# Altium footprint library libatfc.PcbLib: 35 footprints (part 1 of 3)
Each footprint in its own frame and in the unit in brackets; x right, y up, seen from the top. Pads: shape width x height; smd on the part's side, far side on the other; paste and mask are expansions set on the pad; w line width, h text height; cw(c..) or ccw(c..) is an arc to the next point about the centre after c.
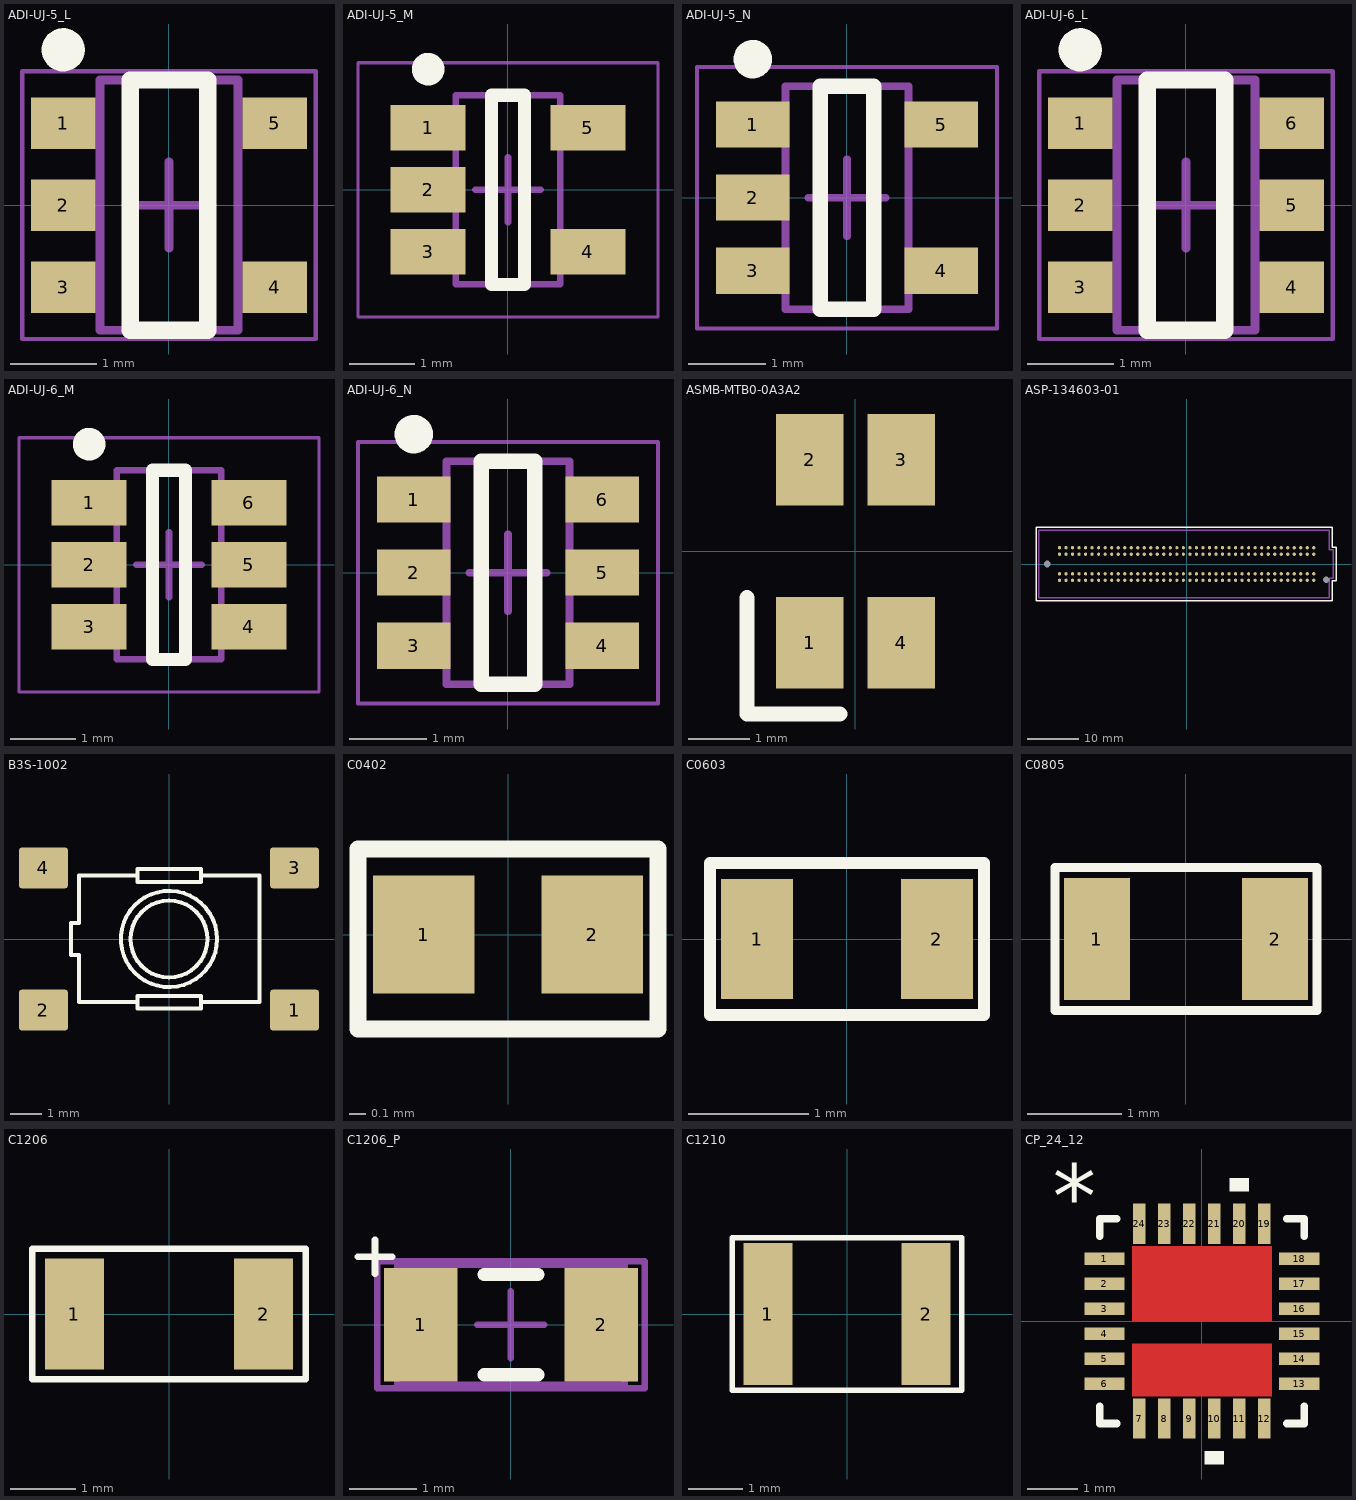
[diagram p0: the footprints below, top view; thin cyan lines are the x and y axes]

## ADI-UJ-5_L [mm] "SOT23, 5-Leads, Body 2.9x1.6mm, Pitch 0.95mm, IPC High Density"
height 1
pads (5):
  rect 0.75x0.6 smd: 1(-1.225,0.95) 2(-1.225,0) 3(-1.225,-0.95) 4(1.225,-0.95) 5(1.225,0.95)
Top Overlay:
  circle w0.25: c-1.225,1.8 r0.125
  lines w0.2: -0.45,-1.45 0.45,-1.45 0.45,1.45 -0.45,1.45 -0.45,-1.45
Mechanical 13:
  lines w0.1: -0.8,-1.45 -0.8,1.45 0.8,1.45 0.8,-1.45 -0.8,-1.45
Mechanical 15:
  lines w0.05: -1.7,-1.55 -1.7,1.55 1.7,1.55 1.7,-1.55 -1.7,-1.55
  lines w0.1: -0.5,0 0.5,0 ; 0,-0.5 0,0.5
3D body: height 1, standoff 0, extent -0.8,-1.45 0.8,1.45

## ADI-UJ-5_M [mm] "SOT23, 5-Leads, Body 2.9x1.6mm, Pitch 0.95mm, IPC Low Density"
height 1
pads (5):
  rect 1.15x0.7 smd: 1(-1.225,0.95) 2(-1.225,0) 3(-1.225,-0.95) 4(1.225,-0.95) 5(1.225,0.95)
Top Overlay:
  circle w0.25: c-1.225,1.85 r0.125
  lines w0.2: -0.25,-1.45 0.25,-1.45 0.25,1.45 -0.25,1.45 -0.25,-1.45
Mechanical 13:
  lines w0.1: -0.8,-1.45 -0.8,1.45 0.8,1.45 0.8,-1.45 -0.8,-1.45
Mechanical 15:
  lines w0.05: -2.3,-1.95 -2.3,1.95 2.3,1.95 2.3,-1.95 -2.3,-1.95
  lines w0.1: -0.5,0 0.5,0 ; 0,-0.5 0,0.5
3D body: height 1, standoff 0, extent -0.8,-1.45 0.8,1.45

## ADI-UJ-5_N [mm] "SOT23, 5-Leads, Body 2.9x1.6mm, Pitch 0.95mm, IPC Medium Density"
height 1
pads (5):
  rect 0.95x0.6 smd: 1(-1.225,0.95) 2(-1.225,0) 3(-1.225,-0.95) 4(1.225,-0.95) 5(1.225,0.95)
Top Overlay:
  circle w0.25: c-1.225,1.8 r0.125
  lines w0.2: -0.35,-1.45 -0.35,1.45 0.35,1.45 0.35,-1.45 -0.35,-1.45
Mechanical 13:
  lines w0.1: -0.8,-1.45 0.8,-1.45 0.8,1.45 -0.8,1.45 -0.8,-1.45
Mechanical 15:
  lines w0.05: -1.95,-1.7 1.95,-1.7 1.95,1.7 -1.95,1.7 -1.95,-1.7
  lines w0.1: -0.5,0 0.5,0 ; 0,-0.5 0,0.5
3D body: height 1, standoff 0, extent -0.8,-1.45 0.8,1.45

## ADI-UJ-6_L [mm] "SOT23, 6-Leads, Body 2.9x1.6mm, Pitch 0.95mm, IPC High Density"
height 1
pads (6):
  rect 0.75x0.6 smd: 1(-1.225,0.95) 2(-1.225,0) 3(-1.225,-0.95) 4(1.225,-0.95) 5(1.225,0) 6(1.225,0.95)
Top Overlay:
  circle w0.25: c-1.225,1.8 r0.125
  lines w0.2: -0.45,-1.45 0.45,-1.45 0.45,1.45 -0.45,1.45 -0.45,-1.45
Mechanical 13:
  lines w0.1: -0.8,-1.45 -0.8,1.45 0.8,1.45 0.8,-1.45 -0.8,-1.45
Mechanical 15:
  lines w0.05: -1.7,-1.55 -1.7,1.55 1.7,1.55 1.7,-1.55 -1.7,-1.55
  lines w0.1: -0.5,0 0.5,0 ; 0,-0.5 0,0.5
3D body: height 1, standoff 0.1, extent -0.8,-1.45 0.8,1.45

## ADI-UJ-6_M [mm] "SOT23, 6-Leads, Body 2.9x1.6mm, Pitch 0.95mm, IPC Low Density"
height 1
pads (6):
  rect 1.15x0.7 smd: 1(-1.225,0.95) 2(-1.225,0) 3(-1.225,-0.95) 4(1.225,-0.95) 5(1.225,0) 6(1.225,0.95)
Top Overlay:
  circle w0.25: c-1.225,1.85 r0.125
  lines w0.2: -0.25,-1.45 0.25,-1.45 0.25,1.45 -0.25,1.45 -0.25,-1.45
Mechanical 13:
  lines w0.1: -0.8,-1.45 -0.8,1.45 0.8,1.45 0.8,-1.45 -0.8,-1.45
Mechanical 15:
  lines w0.05: -2.3,-1.95 -2.3,1.95 2.3,1.95 2.3,-1.95 -2.3,-1.95
  lines w0.1: -0.5,0 0.5,0 ; 0,-0.5 0,0.5
3D body: height 1, standoff 0.1, extent -0.8,-1.45 0.8,1.45

## ADI-UJ-6_N [mm] "SOT23, 6-Leads, Body 2.9x1.6mm, Pitch 0.95mm, IPC Medium Density"
height 1
pads (6):
  rect 0.95x0.6 smd: 1(-1.225,0.95) 2(-1.225,0) 3(-1.225,-0.95) 4(1.225,-0.95) 5(1.225,0) 6(1.225,0.95)
Top Overlay:
  circle w0.25: c-1.225,1.8 r0.125
  lines w0.2: -0.35,-1.45 0.35,-1.45 0.35,1.45 -0.35,1.45 -0.35,-1.45
Mechanical 13:
  lines w0.1: -0.8,-1.45 -0.8,1.45 0.8,1.45 0.8,-1.45 -0.8,-1.45
Mechanical 15:
  lines w0.05: -1.95,-1.7 -1.95,1.7 1.95,1.7 1.95,-1.7 -1.95,-1.7
  lines w0.1: -0.5,0 0.5,0 ; 0,-0.5 0,0.5
3D body: height 1, standoff 0.1, extent -0.8,-1.45 0.8,1.45

## ASMB-MTB0-0A3A2 [mm]
pads (4):
  rect 1.1x1.5 smd: 1(-0.75,-1.5) 2(-0.75,1.5) 3(0.75,1.5) 4(0.75,-1.5)
Top Overlay:
  lines w0.254: -1.778,-0.762 -1.778,-2.667 -0.254,-2.667
3D body "User Library-ASMB-MTB0-0A3A2.STEP": height 1.9, standoff 0, extent -1.395,-1.685 1.405,1.815

## ASP-134603-01 [mil]
pads (162):
  round 25 smd paste+5 mask+2: C1(975,-125) C2(925,-125) C3(875,-125) C4(825,-125) C5(775,-125) C6(725,-125) C7(675,-125) C8(625,-125) C9(575,-125) C10(525,-125) C11(475,-125) C12(425,-125) C13(375,-125) C14(325,-125) C15(275,-125) C16(225,-125) C17(175,-125) C18(125,-125) C19(75,-125) C20(25,-125) C21(-25,-125) C22(-75,-125) C23(-125,-125) C24(-175,-125) C25(-225,-125) C26(-275,-125) C27(-325,-125) C28(-375,-125) C29(-425,-125) C30(-475,-125) C31(-525,-125) C32(-575,-125) C33(-625,-125) C34(-675,-125) C35(-725,-125) C36(-775,-125) C37(-825,-125) C38(-875,-125) C39(-925,-125) C40(-975,-125) D1(975,-75) D2(925,-75) D3(875,-75) D4(825,-75) D5(775,-75) D6(725,-75) D7(675,-75) D8(625,-75) D9(575,-75) D10(525,-75) D11(475,-75) D12(425,-75) D13(375,-75) D14(325,-75) D15(275,-75) D16(225,-75) D17(175,-75) D18(125,-75) D19(75,-75) D20(25,-75) D21(-25,-75) D22(-75,-75) D23(-125,-75) D24(-175,-75) D25(-225,-75) D26(-275,-75) D27(-325,-75) D28(-375,-75) D29(-425,-75) D30(-475,-75) D31(-525,-75) D32(-575,-75) D33(-625,-75) D34(-675,-75) D35(-725,-75) D36(-775,-75) D37(-825,-75) D38(-875,-75) D39(-925,-75) D40(-975,-75) G1(975,75) G2(925,75) G3(875,75) G4(825,75) G5(775,75) G6(725,75) G7(675,75) G8(625,75) G9(575,75) G10(525,75) G11(475,75) G12(425,75) G13(375,75) G14(325,75) G15(275,75) G16(225,75) G17(175,75) G18(125,75) G19(75,75) G20(25,75) G21(-25,75) G22(-75,75) G23(-125,75) G24(-175,75) G25(-225,75) G26(-275,75) G27(-325,75) G28(-375,75) G29(-425,75) G30(-475,75) G31(-525,75) G32(-575,75) G33(-625,75) G34(-675,75) G35(-725,75) G36(-775,75) G37(-825,75) G38(-875,75) G39(-925,75) G40(-975,75) H1(975,125) H2(925,125) H3(875,125) H4(825,125) H5(775,125) H6(725,125) H7(675,125) H8(625,125) H9(575,125) H10(525,125) H11(475,125) H12(425,125) H13(375,125) H14(325,125) H15(275,125) H16(225,125) H17(175,125) H18(125,125) H19(75,125) H20(25,125) H21(-25,125) H22(-75,125) H23(-125,125) H24(-175,125) H25(-225,125) H26(-275,125) H27(-325,125) H28(-375,125) H29(-425,125) H30(-475,125) H31(-525,125) H32(-575,125) H33(-625,125) H34(-675,125) H35(-725,125) H36(-775,125) H37(-825,125) H38(-875,125) H39(-925,125) H40(-975,125)
  round 0 hole 50 unplated: MH1(1070.5,-120) MH2(-1070.5,0)
Top Overlay:
  lines w10: -1155,-280 1115,-280 1115,-130 1145,-130 1145,130 1115,130 1115,280 -1155,280 -1155,-280
Mechanical 1:
  lines w10: -1135,-260 1095,-260 1095,-110 1125,-110 1125,110 1095,110 1095,260 -1135,260 -1135,-260
  text "J1" at -19.57,-20 h30
3D body "459714305.stp": height 259.15, standoff -48.85, extent -1131,-295 1151,283

## B3S-1002 [mm]
height 7.12
pads (4):
  rrect15% 1.55x1.3 smd: 1(3.975,-2.25) 2(-3.975,-2.25) 3(3.975,2.25) 4(-3.975,2.25)
Top Overlay:
  circle w0.127: c0,0 r1.219
  circle w0.127: c0,0 r1.524
  lines w0.127: -1,-2 -2.85,-2 -2.85,-0.5 -3.1,-0.5 -3.1,0.508 -2.85,0.508 -2.85,2.007 -1,2.007 ; -1,-2 -1,-2.2 1.016,-2.2 1.016,-2 ; -1,-2 -1,-1.8 1.016,-1.8 1.016,-2 ; -1,2.007 -1,1.803 1.016,1.803 1.016,2.007 ; -1,2.007 -1,2.21 1.016,2.21 1.016,2.007 ; 1.016,-2 2.87,-2 2.87,2.007 1.016,2.007

## C0402 [mm]
pads (2):
  rect 0.6x0.7 smd: 1(-0.5,0) 2(0.5,0)
Top Overlay:
  lines w0.1: -0.889,-0.561 -0.889,0.508 0.889,0.508 0.889,-0.561 -0.889,-0.561
3D body: height 0.35, standoff 0, extent 0.381,-0.254 0.54,0.254
3D body: height 0.35, standoff 0, extent -0.381,-0.254 0.381,0.254
3D body: height 0.35, standoff 0, extent -0.54,-0.254 -0.381,0.254

## C0603 [mm]
pads (2):
  rect 0.6x1 smd: 1(-0.75,0) 2(0.75,0)
Top Overlay:
  lines w0.1: -1.143,-0.635 1.143,-0.635 1.143,0.635 -1.143,0.635 -1.143,-0.635
3D body: height 0.35, standoff 0, extent -0.508,-0.444 0.508,0.445
3D body: height 0.35, standoff 0, extent 0.508,-0.444 0.762,0.445
3D body: height 0.35, standoff 0, extent -0.762,-0.444 -0.508,0.445

## C0805 [mm]
pads (2):
  rect 0.7x1.3 smd: 1(-0.95,0) 2(0.95,0)
Top Overlay:
  lines w0.1: -1.397,-0.762 -1.397,-0.253 -1.397,0.762 1.397,0.762 1.397,-0.762 -1.397,-0.762
3D body: height 0.35, standoff 0, extent -1.016,-0.603 -0.762,0.603
3D body: height 0.35, standoff 0, extent -0.762,-0.603 0.762,0.603
3D body: height 0.35, standoff 0, extent 0.762,-0.603 1.016,0.603

## C1206 [mm]
pads (2):
  rect 0.9x1.7 smd: 1(-1.45,0) 2(1.45,0)
Top Overlay:
  lines w0.1: -2.1,-1 -2.1,0 -2.1,1 2.1,1 2.1,-1 -2.1,-1
3D body: height 0.55, standoff 0, extent -1.524,-0.762 -1.016,0.762
3D body: height 0.55, standoff 0, extent -1.016,-0.762 1.016,0.762
3D body: height 0.55, standoff 0, extent 1.016,-0.762 1.524,0.762

## C1206_P [mm]
height 1.3
pads (2):
  rect 1.1x1.7 smd: 1(-1.35,0) 2(1.35,0)
Top Overlay:
  lines w0.1: -2.286,1.016 -1.778,1.016 ; -2.032,0.762 -2.032,1.27
  lines w0.2: -0.4,-0.75 0.4,-0.75 ; -0.4,0.75 0.4,0.75
Mechanical 13:
  lines w0.1: -1.7,-0.9 -1.7,0.9 1.7,0.9 1.7,-0.9 -1.7,-0.9
Mechanical 15:
  lines w0.1: -0.5,0 0.5,0 ; 0,-0.5 0,0.5 ; -2,-0.95 -2,0.95 2,0.95 2,-0.95 -2,-0.95
3D body: height 1.3, standoff 0, extent -1.7,-0.9 1.7,0.9

## C1210 [mm]
pads (2):
  rect 0.9x2.6 smd: 1(-1.45,0) 2(1.45,0)
Top Overlay:
  lines w0.1: -2.1,-1.397 2.1,-1.397 2.1,1.397 -2.1,1.397 -2.1,0 -2.1,-1.397
3D body: height 0.55, standoff 0, extent 1.016,-1.143 1.524,1.143
3D body: height 0.55, standoff 0, extent -1.016,-1.143 1.016,1.143
3D body: height 0.55, standoff 0, extent -1.524,-1.143 -1.016,1.143

## CP_24_12 [mm]
pads (24):
  rect 0.805x0.25 smd: 1(-1.952,1.25) 2(-1.952,0.75) 3(-1.952,0.25) 4(-1.952,-0.25) 5(-1.952,-0.75) 6(-1.952,-1.25) 13(1.952,-1.25) 14(1.952,-0.75) 15(1.952,-0.25) 16(1.952,0.25) 17(1.952,0.75) 18(1.952,1.25)
  rect 0.25x0.805 smd: 7(-1.25,-1.952) 8(-0.75,-1.952) 9(-0.25,-1.952) 10(0.25,-1.952) 11(0.75,-1.952) 12(1.25,-1.952) 19(1.25,1.952) 20(0.75,1.952) 21(0.25,1.952) 22(-0.25,1.952) 23(-0.75,1.952) 24(-1.25,1.952)
Top Layer:
  region: -1.4,-1.5 -1.4,-0.45 1.4,-0.45 1.4,-1.5
  region: -1.4,0 -1.4,1.5 1.4,1.5 1.4,0
Top Overlay:
  region: 0.941,2.609 0.56,2.609 0.56,2.863 0.941,2.863
  region: 0.44,-2.609 0.059,-2.609 0.059,-2.863 0.44,-2.863
  lines w0.152: -2.05,-1.708 -2.05,-2.05 -1.708,-2.05 ; -2.05,1.708 -2.05,2.05 -1.708,2.05 ; 1.708,-2.05 2.05,-2.05 2.05,-1.708 ; 1.708,2.05 2.05,2.05 2.05,1.708
  text "*" at -2.99,1.881 h1.27
Top Paste:
  region: -1.4,-1.5 -1.4,-0.45 1.4,-0.45 1.4,-1.5
  region: -1.4,0 -1.4,1.5 1.4,1.5 1.4,0
Top Solder:
  region: -1.4,-1.5 -1.4,-0.45 1.4,-0.45 1.4,-1.5
  region: -1.4,0 -1.4,1.5 1.4,1.5 1.4,0
Mechanical 13:
  text "*" at -2.99,1.881 h1.27
3D body: height 0.25, standoff 0, extent 0,0 0.254,0.254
